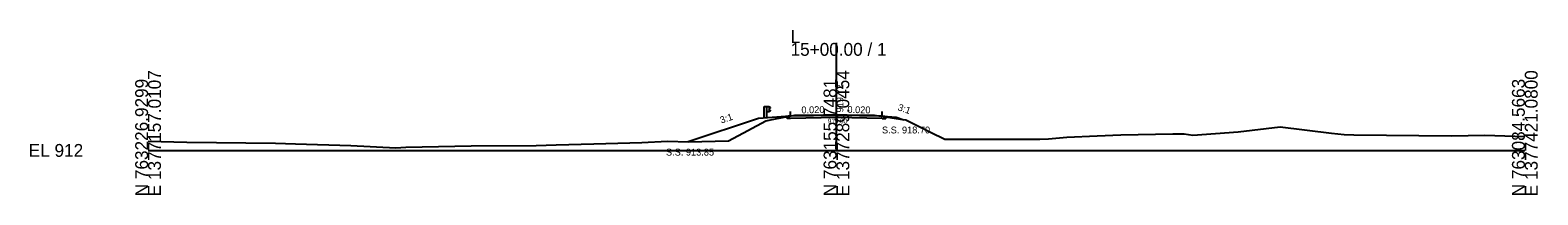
# Model space of a CAD drawing. Extents: x -26 to 303, y -10 to 6523.
# Drawn here: x -25.7 to 302.8, y 4990.3 to 5026.2 of the extents above; entities that cross this region are included whole.
import ezdxf

# ---------------------------------------------------------------- set-up
doc = ezdxf.new("R2010")
doc.units = 0
for name, color, linetype in [('Exist Cross Section Cell', 7, 'Continuous'), ('Exist XS Center Line Elevation Label', 7, 'Continuous'), ('Exist XS Ground Line', 7, 'Continuous'), ('Prop XS Dump Level', 7, 'Continuous'), ('Prop XS Elevation Labels', 7, 'Continuous'), ('Prop XS EOT Tick Mark', 7, 'Continuous'), ('Prop XS Finish Grade', 7, 'Continuous'), ('Prop XS Finish Grade Earthwork', 7, 'Continuous'), ('Prop XS Finish Grade Pavement', 7, 'Continuous'), ('Prop XS Guardrail', 7, 'Continuous'), ('Prop XS Pvmt Edge Slope', 7, 'Continuous'), ('Prop XS SE Text', 7, 'Continuous'), ('Prop XS Side Slope Text', 7, 'Continuous'), ('Prop XS SS Elevation Text', 7, 'Continuous'), ('Prop XS Subgrade Earthwork', 7, 'Continuous')]:
    doc.layers.add(name, color=color, linetype=linetype)

msp = doc.modelspace()

# ---------------------------------------------------------------- linework, layer by layer
at = {"layer": 'Exist Cross Section Cell'}
for p, q in [((150, 5000), (150, 5023.43)), ((0, 5000), (150, 5000)), ((150, 5000), (300, 5000))]:
    msp.add_line(p, q, dxfattribs=at)
at = {"layer": 'Exist XS Ground Line'}
for p, q in [((134.61, 5006.42), (136.72, 5006.91)), ((136.72, 5006.91), (140.96, 5007.67)), ((140.96, 5007.67), (144.63, 5007.72)), ((144.63, 5007.72), (149.62, 5007.81)), ((149.62, 5007.81), (150, 5007.8)), ((150, 5007.8), (154.66, 5007.72)), ((154.66, 5007.72), (158.3, 5007.66)), ((158.3, 5007.66), (163.95, 5006.8)), ((126.48, 5002.1), (130.72, 5004.33)), ((130.72, 5004.33), (134.61, 5006.42)), ((163.95, 5006.8), (165.11, 5006.66)), ((165.11, 5006.66), (170.52, 5003.98)), ((170.52, 5003.98), (173.65, 5002.45)), ((211.95, 5003.37), (223.3, 5003.58)), ((223.3, 5003.58), (225.78, 5003.59)), ((225.78, 5003.59), (227.68, 5003.36)), ((227.68, 5003.36), (237.57, 5004.06)), ((237.57, 5004.06), (246.67, 5005.11)), ((246.67, 5005.11), (257.87, 5003.78)), ((257.87, 5003.78), (260.65, 5003.48)), ((0, 5002), (8.47, 5001.83)), ((8.47, 5001.83), (27.74, 5001.6)), ((27.74, 5001.6), (32.14, 5001.41)), ((32.14, 5001.41), (44.22, 5001.06)), ((44.22, 5001.06), (54.01, 5000.59)), ((54.01, 5000.59), (56.14, 5000.74)), ((56.14, 5000.74), (70.42, 5000.97)), ((70.42, 5000.97), (84.54, 5001.09)), ((84.54, 5001.09), (88.9, 5001.19)), ((88.9, 5001.19), (97.13, 5001.42)), ((97.13, 5001.42), (107.63, 5001.72)), ((107.63, 5001.72), (113.16, 5002)), ((113.16, 5002), (117.75, 5001.85)), ((117.75, 5001.85), (126.48, 5002.1)), ((173.65, 5002.45), (191.51, 5002.48)), ((191.51, 5002.48), (194.31, 5002.45)), ((194.31, 5002.45), (196.23, 5002.51)), ((196.23, 5002.51), (200.18, 5002.92)), ((200.18, 5002.92), (206.78, 5003.17)), ((206.78, 5003.17), (211.95, 5003.37)), ((260.65, 5003.48), (262.76, 5003.37)), ((262.76, 5003.37), (283.99, 5003.19)), ((283.99, 5003.19), (291.29, 5003.35)), ((291.29, 5003.35), (300, 5003))]:
    msp.add_line(p, q, dxfattribs=at)
at = {"layer": 'Prop XS Dump Level'}
for p, q in [((140, 5007.52), (150, 5007.72)), ((150, 5007.72), (160, 5007.52))]:
    msp.add_line(p, q, dxfattribs=at)
at = {"layer": 'Prop XS EOT Tick Mark'}
for p, q in [((140, 5007.52), (140, 5008.52)), ((160, 5007.52), (160, 5008.52))]:
    msp.add_line(p, q, dxfattribs=at)
at = {"layer": 'Prop XS Finish Grade'}
for p, q in [((140, 5007.52), (138.9, 5007.43)), ((160, 5007.52), (161.1, 5007.43))]:
    msp.add_line(p, q, dxfattribs=at)
at = {"layer": 'Prop XS Finish Grade Earthwork'}
for p, q in [((133, 5006.96), (117.68, 5001.85)), ((137, 5007.28), (133, 5006.96)), ((138.9, 5007.43), (137, 5007.28)), ((161.1, 5007.43), (163, 5007.28)), ((163, 5007.28), (164.72, 5006.7))]:
    msp.add_line(p, q, dxfattribs=at)
at = {"layer": 'Prop XS Finish Grade Pavement'}
for p, q in [((140, 5007.52), (150, 5007.72)), ((150, 5007.72), (160, 5007.52))]:
    msp.add_line(p, q, dxfattribs=at)
at = {"layer": 'Prop XS Guardrail'}
for p, q in [((134.25, 5009.56), (134.75, 5009.56)), ((134.25, 5007.06), (134.25, 5009.56)), ((134.75, 5009.56), (135.25, 5009.56)), ((134.75, 5009.56), (134.75, 5007.06)), ((135.25, 5008.42), (134.75, 5008.42)), ((135.25, 5009.56), (135.54, 5009.36)), ((135.54, 5009.24), (135.25, 5009.04)), ((135.25, 5009.04), (135.25, 5008.94)), ((135.25, 5008.94), (135.54, 5008.74)), ((135.54, 5008.62), (135.25, 5008.42)), ((135.54, 5009.36), (135.57, 5009.3)), ((135.57, 5009.3), (135.54, 5009.24)), ((135.54, 5008.74), (135.57, 5008.68)), ((135.57, 5008.68), (135.54, 5008.62))]:
    msp.add_line(p, q, dxfattribs=at)
at = {"layer": 'Prop XS Pvmt Edge Slope'}
for p, q in [((140, 5007.52), (139.4, 5006.92)), ((160, 5007.52), (160.6, 5006.92))]:
    msp.add_line(p, q, dxfattribs=at)
at = {"layer": 'Prop XS Subgrade Earthwork'}
for p, q in [((139.4, 5006.92), (138.9, 5007.43)), ((140, 5006.94), (139.4, 5006.92)), ((150, 5007.14), (140, 5006.94)), ((160, 5006.94), (150, 5007.14)), ((160, 5006.94), (160.6, 5006.92)), ((160.6, 5006.92), (161.1, 5007.43))]:
    msp.add_line(p, q, dxfattribs=at)

# ---------------------------------------------------------------- texts
at = {"layer": 'Exist Cross Section Cell'}
for s, p in [('15+00.00 / 1', (140, 5020.63)), ('L', (140, 5023.43)), ('EL 912', (-26, 4998.6))]:
    msp.add_text(s, height=2.8, dxfattribs=at).set_placement(p)
for s, p in [('E 1377157.0107', (2.8, 4990)), ('E 1377289.0454', (152.8, 4990)), ('E 1377421.0800', (302.8, 4990)), ('N 763226.9299', (0, 4990)), ('N 763155.7481', (150, 4990)), ('N 763084.5663', (300, 4990))]:
    msp.add_text(s, height=2.8, rotation=90, dxfattribs=at).set_placement(p)
at = {"layer": 'Exist XS Center Line Elevation Label'}
msp.add_text('919.80', height=0.998, dxfattribs=at).set_placement((148.11, 5005.91))
at = {"layer": 'Prop XS Dump Level'}
for p in [(137, 5007.24), (163, 5007.24)]:
    msp.add_text('Case1', height=0.04, dxfattribs=at).set_placement(p)
at = {"layer": 'Prop XS Elevation Labels'}
msp.add_text(' 919.72', height=1.5, rotation=90, dxfattribs=at).set_placement((151.5, 5007.72))
at = {"layer": 'Prop XS SE Text'}
for rotation, p in [(1.1458, (142.38, 5008.07)), (358.8542, (152.38, 5008.17))]:
    msp.add_text('0.020', height=1.5, rotation=rotation, dxfattribs=at).set_placement(p)
at = {"layer": 'Prop XS Side Slope Text'}
for rotation, p in [(18.4349, (124.92, 5005.84)), (341.5651, (163.25, 5008.78))]:
    msp.add_text('3:1', height=1.5, rotation=rotation, dxfattribs=at).set_placement(p)
at = {"layer": 'Prop XS SS Elevation Text'}
for s, p in [('S.S. 918.70', (159.93, 5003.7)), ('S.S. 913.85', (112.85, 4998.88))]:
    msp.add_text(s, height=1.5, dxfattribs=at).set_placement(p)

doc.saveas('drawing.dxf')
